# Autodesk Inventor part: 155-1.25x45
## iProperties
Created: 2007-06
Part Number: 155-1.25x45
Document SubType Name: Modeling
Designer: btaylor
Density: 1 g/cm^3
Author: btaylor
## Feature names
1. Sweep1
2. Extrusion1
3. Extrusion2
4. Fillet1
5. Fillet2
6. Extrusion3
7. Extrusion4
8. Sweep2
9. Fillet3
10. Fillet4
11. Chamfer1
12. Chamfer2
13. Fillet5
14. Fillet6
